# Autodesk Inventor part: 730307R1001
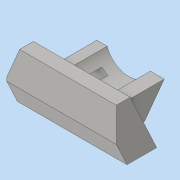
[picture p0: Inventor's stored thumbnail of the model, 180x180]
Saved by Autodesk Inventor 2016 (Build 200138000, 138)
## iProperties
Created: 2023-03
Part Number: 730307R1001
Material: 일반
Document SubType Name: Modeling
Designer: PC-1-11
Density: 1 g/cm^3
Appearance: 기본값
Author: PC-1-11
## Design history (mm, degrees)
sketch "스케치1"
  geometry: L1 (0, 0)-(0, -28.688); L2 (0, -28.688)-(55, -3.041); L3 (55, -3.041)-(55, 10.312); L4 (55, 10.312)-(22.115, 10.312); L5 (22.115, 10.312)-(0, 0)
  constraints: 10 end point, 2 parallel, 1 perpendicular, 1 vertical
  dimensions: "d0" = 39 distance from line of L1.end L4; "d2" = 55 distance between parallel lines of L1 L3; "d3" = 26 distance between parallel lines of L2 L5; "d4" = 25 deg angle of L2 L4
extrude "돌출1" new body sketch "스케치1" stored distance "d5" = 106; taper "d6" = 0 deg
node "작업 평면1"
sketch "스케치3"
  geometry: L1 (0, 32.885)-(0, -22.115) reference; L2 (0, 0)-(106, 0) reference; L3 (106, 32.885)-(106, 0) reference; L4 (0, 32.885)-(106, 32.885) reference; L5 (0, 0)-(0, 32.885) reference; L6 (106, -22.115)-(0, -22.115) reference; L7 (106, 0)-(106, -22.115) reference; L8 (0, 0)-(106, 0) reference; L9 (0, -22.115)-(0, 0) reference; L10 (13, -22.115)-(32.101, 22.885); L11 (32.101, 22.885)-(42.143, 22.885); L12 (0, -22.115)-(106, -22.115) reference; L13 (78.182, -22.115)-(97.283, 22.885); L14 (97.283, 22.885)-(83.857, 22.885); L15 (13, -22.115)-(78.182, -22.115); A1 r 22 centre (63, 29.885) between (42.143, 22.885) and (83.857, 22.885); 1 further point
  constraints: 10 end point, 2 parallel, 2 point on circle, 2 point on line, 1 centre point, 1 collinear
  dimensions: "d8" = 67 deg angle of L6 L13; "d9" = 13 distance from line of L10.start L1; "d10" = 45 distance between parallel lines of L11 L6; "d11" = 60 distance between parallel lines of L13 L10; "d12" = 43 distance from line of A1.centre L3; "d13" = 3 distance from line of L4 A1.centre; "d14" = 22 radius of A1
extrude "돌출2" join sketch "스케치3" stored distance "d15" = 106; taper "d16" = 0 deg
sketch "스케치4"
  geometry: L1 (32.101, 22.885)-(13, -22.115) reference; L2 (0, 32.885)-(0, -22.115) reference; L3 (0, 3.564)-(0, 32.885); L4 (0, 32.885)-(12.446, 32.885); L5 (0, 32.885)-(106, 32.885) reference; L6 (12.446, 32.885)-(0, 3.564); 1 further point
  constraints: 6 end point, 2 point on line, 1 collinear, 1 parallel
  dimensions: "d17" = 22 distance between parallel lines of L1 L6
extrude "돌출3" cut sketch "스케치4" stored distance "d18" = 106; taper "d19" = 0 deg
sketch "스케치5"
  geometry: L1 (-33.688, 36)-(-20.688, 36); L2 (-20.688, 36)-(-20.688, 7); L3 (-20.688, 7)-(-33.688, 7); L4 (-33.688, 7)-(-33.688, 36); L5 (-44.688, 45)-(-44.688, 0) reference; L6 (-44.688, 45)-(-7.704, 45) reference; 1 further point
  constraints: 8 end point, 2 parallel, 1 horizontal, 1 perpendicular
  dimensions: "d20" = 13 distance between parallel lines of L2 L4; "d21" = 11 distance between parallel lines of L5 L4; "d22" = 9 distance between parallel lines of L6 L1; "d23" = 29 distance between parallel lines of L3 L1
extrude "돌출4" cut sketch "스케치5" distance "d24" = 54; taper "d25" = 0 deg
node "솔리드1"
node "투영된 루프1"
node "투영된 루프2"
other parameters: "d7" = -55
